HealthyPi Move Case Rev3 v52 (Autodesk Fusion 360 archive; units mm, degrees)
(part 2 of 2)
create_component "CreateComponent2"
create_component "CreateComponent3"
create_component "CreateComponent5"
create_component "CreateComponent7"
create_component "CreateComponent8"
create_component "CreateComponent9"
create_component "CreateComponent16"
create_component "CreateComponent21"
create_component "CreateComponent22"
create_component "CreateComponent24"
create_component "CreateComponent25"
create_component "CreateComponent26"
create_component "CreateComponent27"
create_component "CreateComponent28"
create_component "CreateComponent29"
create_component "CreateComponent30"
as_built_joint "As-built1"
create_component "CreateComponent31"
create_component "CreateComponent1"
create_component "CreateComponent35"
create_component "CreateComponent37"
create_component "CreateComponent38"
create_component "CreateComponent41"
create_component "CreateComponent42"
create_component "CreateComponent43"
create_component "CreateComponent44"
create_component "CreateComponent45"
create_component "CreateComponent46"
create_component "CreateComponent49"
create_component "CreateComponent51"
create_component "CreateComponent53"
create_component "CreateComponent54"
create_component "CreateComponent56"
create_component "CreateComponent57"
create_component "CreateComponent58"
create_component "CreateComponent59"
create_component "CreateComponent60"
named bodies: "Board"

design "pc_healthypi_move_bottom_pcb_v2"
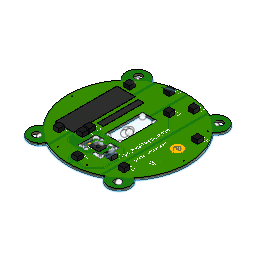
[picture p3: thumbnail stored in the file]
sketch "Outline" plane through (0, 0, 0) normal (0, 0, 1) x axis (1, 0, 0)
  line L1 (5.8203, -2.7998) -> (5.5496, -2.9972)
  line L2 (7, -1.2) -> (6.8643, -1.5063)
  line L3 (27.4, -1.2) -> (27, -1.4)
  line L4 (27.5357, -1.5063) -> (27.4, -1.2)
  line L5 (34.2527, 2.2023) -> (34.4146, 1.9091)
  line L6 (33.1, 3.4) -> (33.3707, 3.2026)
  line L7 (33.1, 30.9) -> (34.236, 29.4195)
  line L8 (28.8504, 37.2972) -> (29.1372, 37.4702)
  line L9 (28.0949, 36.6383) -> (28.3272, 36.8796)
  line L10 (27.8845, 36.3776) -> (28.0949, 36.6383)
  line L11 (27.4, 35.5) -> (27.5357, 35.8063)
  line L12 (7, 35.5) -> (8.7465, 36.3144)
  line L13 (6.3051, 36.6383) -> (6.5155, 36.3776)
  line L14 (6.0728, 36.8796) -> (6.3051, 36.6383)
  line L15 (1.0293, 31.0974) -> (0.7768, 31.3176)
  line L16 (1.3, 30.9) -> (1.0293, 31.0974)
  line L17 (1.3, 3.4) -> (0.164, 4.8805)
  line L18 (19.55, 11.6) -> (15.05, 11.6)
  line L19 (19.5805, 11.6013) -> (19.55, 11.6)
  line L20 (19.9, 24.35) -> (19.9, 11.95)
  line L21 (19.8987, 24.3805) -> (19.9, 24.35)
  line L22 (15.05, 24.7) -> (19.55, 24.7)
  line L23 (15.0195, 24.6987) -> (15.05, 24.7)
  line L24 (14.7, 11.95) -> (14.7, 24.35)
  line L25 (15.9, 3.4) -> (13.7, 3.4)
  line L26 (15.9305, 3.4013) -> (15.9, 3.4)
  line L27 (16.25, 4.05) -> (16.25, 3.75)
  line L28 (16.2487, 4.0805) -> (16.25, 4.05)
  line L29 (14.75, 4.4) -> (15.9, 4.4)
  line L30 (14.7151, 4.4015) -> (14.75, 4.4)
  line L31 (14.35, 8.45) -> (14.35, 4.8)
  line L32 (14.3513, 8.4805) -> (14.35, 8.45)
  line L33 (15.95, 8.8) -> (14.7, 8.8)
  line L34 (15.9761, 8.8011) -> (15.95, 8.8)
  line L35 (16.25, 9.5) -> (16.25, 9.1)
  line L36 (16.2489, 9.5261) -> (16.25, 9.5)
  line L37 (13.7, 9.8) -> (15.95, 9.8)
  line L38 (13.6695, 9.7987) -> (13.7, 9.8)
  line L39 (13.35, 3.75) -> (13.35, 9.45)
  line L40 (21, 3.4) -> (18.8, 3.4)
  line L41 (21.0305, 3.4013) -> (21, 3.4)
  line L42 (21.35, 9.45) -> (21.35, 3.75)
  line L43 (21.3487, 9.4805) -> (21.35, 9.45)
  line L44 (18.8, 9.8) -> (21, 9.8)
  line L45 (18.7695, 9.7987) -> (18.8, 9.8)
  line L46 (18.45, 9.15) -> (18.45, 9.45)
  line L47 (18.4513, 9.1195) -> (18.45, 9.15)
  line L48 (20, 8.8) -> (18.8, 8.8)
  line L49 (20.0305, 8.7987) -> (20, 8.8)
  line L50 (20.35, 4.75) -> (20.35, 8.45)
  line L51 (20.3487, 4.7195) -> (20.35, 4.75)
  line L52 (18.8, 4.4) -> (20, 4.4)
  line L53 (18.7695, 4.3987) -> (18.8, 4.4)
  line L54 (18.45, 3.75) -> (18.45, 4.05)
  arc A1 centre (3.4248, 0.2014) radius 3.84 clockwise from (5.5496, -2.9972) to (1.3, 3.4)
  arc A2 centre (3.4248, 0.2014) radius 3.84 clockwise from (6.8643, -1.5063) to (5.8203, -2.7998)
  arc A3 centre (17.1921, 17.9099) radius 21.6579 clockwise from (27, -1.4) to (7, -1.2)
  arc A4 centre (30.9752, 0.2014) radius 3.84 clockwise from (34.4146, 1.9091) to (27.5357, -1.5063)
  arc A5 centre (30.9752, 0.2014) radius 3.84 clockwise from (33.3707, 3.2026) to (34.2527, 2.2023)
  arc A6 centre (16.7133, 17.15) radius 21.3912 clockwise from (34.236, 29.4195) to (33.1, 3.4)
  arc A7 centre (30.9752, 34.0986) radius 3.84 clockwise from (29.1372, 37.4702) to (33.1, 30.9)
  arc A8 centre (30.9754, 34.0983) radius 3.8404 clockwise from (28.3272, 36.8796) to (28.8504, 37.2972)
  arc A9 centre (30.9751, 34.0985) radius 3.84 clockwise from (27.5357, 35.8063) to (27.8845, 36.3776)
  arc A10 centre (17.2, 15.906) radius 22.0899 clockwise from (8.7465, 36.3144) to (27.4, 35.5)
  arc A11 centre (3.4247, 34.0986) radius 3.8401 clockwise from (6.5155, 36.3776) to (7, 35.5)
  arc A12 centre (3.4248, 34.0986) radius 3.84 clockwise from (0.7768, 31.3176) to (6.0728, 36.8796)
  arc A13 centre (17.6866, 17.15) radius 21.3912 clockwise from (0.164, 4.8805) to (1.3, 30.9)
  arc A14 centre (15.05, 11.95) radius 0.35 clockwise from (15.05, 11.6) to (14.7, 11.95)
  arc A15 centre (19.55, 11.95) radius 0.35 clockwise from (19.9, 11.95) to (19.5805, 11.6013)
  arc A16 centre (19.55, 24.35) radius 0.35 clockwise from (19.55, 24.7) to (19.8987, 24.3805)
  arc A17 centre (15.05, 24.35) radius 0.35 clockwise from (14.7, 24.35) to (15.0195, 24.6987)
  arc A18 centre (13.7, 3.75) radius 0.35 clockwise from (13.7, 3.4) to (13.35, 3.75)
  arc A19 centre (15.9, 3.75) radius 0.35 clockwise from (16.25, 3.75) to (15.9305, 3.4013)
  arc A20 centre (15.9, 4.05) radius 0.35 clockwise from (15.9, 4.4) to (16.2487, 4.0805)
  arc A21 centre (14.75, 4.8) radius 0.4 clockwise from (14.7151, 4.4015) to (14.35, 4.8)
  arc A22 centre (14.7, 8.45) radius 0.35 clockwise from (14.3513, 8.4805) to (14.7, 8.8)
  arc A23 centre (15.95, 9.1) radius 0.3 clockwise from (16.25, 9.1) to (15.9761, 8.8011)
  arc A24 centre (15.95, 9.5) radius 0.3 clockwise from (15.95, 9.8) to (16.2489, 9.5261)
  arc A25 centre (13.7, 9.45) radius 0.35 clockwise from (13.35, 9.45) to (13.6695, 9.7987)
  arc A26 centre (18.8, 3.75) radius 0.35 clockwise from (18.8, 3.4) to (18.45, 3.75)
  arc A27 centre (21, 3.75) radius 0.35 clockwise from (21.35, 3.75) to (21.0305, 3.4013)
  arc A28 centre (21, 9.45) radius 0.35 clockwise from (21, 9.8) to (21.3487, 9.4805)
  arc A29 centre (18.8, 9.45) radius 0.35 clockwise from (18.45, 9.45) to (18.7695, 9.7987)
  arc A30 centre (18.8, 9.15) radius 0.35 clockwise from (18.8, 8.8) to (18.4513, 9.1195)
  arc A31 centre (20, 8.45) radius 0.35 clockwise from (20.0305, 8.7987) to (20.35, 8.45)
  arc A32 centre (20, 4.75) radius 0.35 clockwise from (20.3487, 4.7195) to (20, 4.4)
  arc A33 centre (18.8, 4.05) radius 0.35 clockwise from (18.45, 4.05) to (18.7695, 4.3987)
canvas "Canvas1" bodies "Board"
canvas "Canvas2" bodies "Board"
pcbhole "PCBHole1" HoleDepth 0.8 HoleDiameter 2.5 TipAngle 10313.2
pcbhole "PCBHole2" HoleDepth 0.8 HoleDiameter 2.5 TipAngle 10313.2
pcbhole "PCBHole3" HoleDepth 0.8 HoleDiameter 2.5 TipAngle 10313.2
pcbhole "PCBHole4" HoleDepth 0.8 HoleDiameter 2.5 TipAngle 10313.2
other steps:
box_primitive "BoxPrimitive1" DistanceX 14.25 DistanceY 2.04 DistanceZ 0.1 OffsetDistanceX 0 OffsetDistanceY 0
box_primitive "BoxPrimitive1" DistanceX 21.63 DistanceY 6.45 DistanceZ 0.1 OffsetDistanceX 0 OffsetDistanceY 0
box_primitive "BoxPrimitive1" DistanceX 3.65 DistanceY 3.127 DistanceZ 0.1 OffsetDistanceX 0 OffsetDistanceY 0
base_feature "Base Feature"
box_primitive "BoxPrimitive1" DistanceX 2 DistanceY 2 DistanceZ 1.365 OffsetDistanceX 0 OffsetDistanceY 0
extrude "Extrude1" sketch "Outline" blind 0.8 bodies "Board"
pcbextrude "PCBExtrude1"
create_component "CreateComponent1"
create_component "CreateComponent2"
create_component "CreateComponent4"
as_built_joint "As-built1"
create_component "CreateComponent5"
create_component "CreateComponent6"
create_component "CreateComponent7"
create_component "CreateComponent8"
create_component "CreateComponent9"
named bodies: "Board"

design "pc_healthypi_move_sensor_dual"
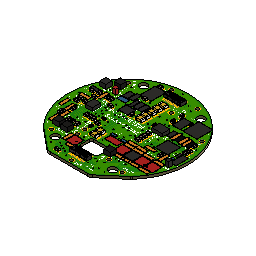
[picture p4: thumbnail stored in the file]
sketch "Outline" plane through (0, 0, 0) normal (0, 0, 1) x axis (1, 0, 0)
  line L1 (12.1, 0.4) -> (5.2, 6.1)
  line L2 (12.1693, 0.3516) -> (12.1, 0.4)
  line L3 (25.5, 0) -> (13.6, 0)
  line L4 (25.5727, -0.0005) -> (25.5, 0)
  line L5 (33.3, 6) -> (26.8, 0.4)
  line L6 (33.4, 6.1) -> (33.3, 6)
  line L7 (33.6273, 6.3481) -> (33.4, 6.1)
  line L8 (3.9028, 30.851) -> (4.9727, 32.1488)
  line L9 (21.6, 6.1) -> (17, 6.1)
  line L10 (21.661, 6.1027) -> (21.6, 6.1)
  line L11 (22.3, 9.8) -> (22.3, 6.8)
  line L12 (22.2973, 9.861) -> (22.3, 9.8)
  line L13 (17, 10.5) -> (21.6, 10.5)
  line L14 (16.939, 10.4973) -> (17, 10.5)
  line L15 (16.3, 6.8) -> (16.3, 9.8)
  arc A1 centre (13.3676, 2.1412) radius 2.1538 clockwise from (13.6, 0) to (12.1693, 0.3516)
  arc A2 centre (25.5512, 2.146) radius 2.1466 clockwise from (26.8, 0.4) to (25.5727, -0.0005)
  arc A3 centre (19.3, 19.2484) radius 19.2793 clockwise from (4.9727, 32.1488) to (33.6273, 6.3481)
  arc A4 centre (19.3, 19.2484) radius 19.2793 clockwise from (5.2, 6.1) to (3.9028, 30.851)
  arc A5 centre (17, 6.8) radius 0.7 clockwise from (17, 6.1) to (16.3, 6.8)
  arc A6 centre (21.6, 6.8) radius 0.7 clockwise from (22.3, 6.8) to (21.661, 6.1027)
  arc A7 centre (21.6, 9.8) radius 0.7 clockwise from (21.6, 10.5) to (22.2973, 9.861)
  arc A8 centre (17, 9.8) radius 0.7 clockwise from (16.3, 9.8) to (16.939, 10.4973)
canvas "Canvas1" bodies "Board"
canvas "Canvas2" bodies "Board"
pcbhole "PCBHole9" HoleDepth 0.8 HoleDiameter 2.5 TipAngle 10313.2
pcbhole "PCBHole10" HoleDepth 0.8 HoleDiameter 2.5 TipAngle 10313.2
pcbhole "PCBHole11" HoleDepth 0.8 HoleDiameter 2.5 TipAngle 10313.2
pcbhole "PCBHole12" HoleDepth 0.8 HoleDiameter 2.5 TipAngle 10313.2
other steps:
box_primitive "BoxPrimitive1" DistanceX 3.1 DistanceY 2.6 DistanceZ 0.1 OffsetDistanceX 0 OffsetDistanceY 0
box_primitive "BoxPrimitive1" DistanceX 2.997 DistanceY 1.017 DistanceZ 0.1 OffsetDistanceX 0 OffsetDistanceY 0
box_primitive "BoxPrimitive1" DistanceX 3.856 DistanceY 4.256 DistanceZ 1 OffsetDistanceX 0 OffsetDistanceY 0
box_primitive "BoxPrimitive1" DistanceX 14.25 DistanceY 2.04 DistanceZ 0.1 OffsetDistanceX 0 OffsetDistanceY 0
box_primitive "BoxPrimitive1" DistanceX 21.63 DistanceY 6.45 DistanceZ 0.1 OffsetDistanceX 0 OffsetDistanceY 0
base_feature "Base Feature1"
base_feature "Base Feature1"
box_primitive "BoxPrimitive1" DistanceX 5.175 DistanceY 4.55 DistanceZ 0.1 OffsetDistanceX 0 OffsetDistanceY 0
box_primitive "BoxPrimitive1" DistanceX 1.85 DistanceY 1.45 DistanceZ 1 OffsetDistanceX 0 OffsetDistanceY 0
box_primitive "BoxPrimitive1" DistanceX 2.515 DistanceY 3.302 DistanceZ 1 OffsetDistanceX 0 OffsetDistanceY 0
box_primitive "BoxPrimitive1" DistanceX 1.85 DistanceY 0.7 DistanceZ 1 OffsetDistanceX 0 OffsetDistanceY 0
box_primitive "BoxPrimitive1" DistanceX 3.815 DistanceY 2.6 DistanceZ 0.1 OffsetDistanceX 0 OffsetDistanceY 0
box_primitive "BoxPrimitive1" DistanceX 2.743 DistanceY 1.397 DistanceZ 0.1 OffsetDistanceX 0 OffsetDistanceY 0
box_primitive "BoxPrimitive1" DistanceX 2.743 DistanceY 1.397 DistanceZ 0.1 OffsetDistanceX 0 OffsetDistanceY 0
base_feature "Base Feature1"
base_feature "Base Feature1"
box_primitive "BoxPrimitive1" DistanceX 0.75 DistanceY 1.7 DistanceZ 0.1 OffsetDistanceX 0 OffsetDistanceY 0
box_primitive "BoxPrimitive1" DistanceX 2.451 DistanceY 1.351 DistanceZ 0.1 OffsetDistanceX 0 OffsetDistanceY 0
box_primitive "BoxPrimitive1" DistanceX 2.997 DistanceY 1.017 DistanceZ 0.1 OffsetDistanceX 0 OffsetDistanceY 0
box_primitive "BoxPrimitive1" DistanceX 3.003 DistanceY 3 DistanceZ 0.1 OffsetDistanceX 0 OffsetDistanceY 0
box_primitive "BoxPrimitive1" DistanceX 2.75 DistanceY 2.25 DistanceZ 1 OffsetDistanceX 0 OffsetDistanceY 0
box_primitive "BoxPrimitive1" DistanceX 8.8 DistanceY 5.55 DistanceZ 0.1 OffsetDistanceX 0 OffsetDistanceY 0
box_primitive "BoxPrimitive1" DistanceX 4.027 DistanceY 1.9 DistanceZ 0.1 OffsetDistanceX 0 OffsetDistanceY 0
box_primitive "BoxPrimitive1" DistanceX 2.45 DistanceY 1.65 DistanceZ 0.1 OffsetDistanceX 0 OffsetDistanceY 0
box_primitive "BoxPrimitive1" DistanceX 4.87 DistanceY 3.55 DistanceZ 0.1 OffsetDistanceX 0 OffsetDistanceY 0
box_primitive "BoxPrimitive1" DistanceX 4.127 DistanceY 4.127 DistanceZ 0.1 OffsetDistanceX 0 OffsetDistanceY 0
box_primitive "BoxPrimitive1" DistanceX 2.743 DistanceY 1.397 DistanceZ 0.1 OffsetDistanceX 0 OffsetDistanceY 0
base_feature "Base Feature1"
box_primitive "BoxPrimitive1" DistanceX 1.1 DistanceY 1.1 DistanceZ 1.654 OffsetDistanceX 0 OffsetDistanceY 0
box_primitive "BoxPrimitive1" DistanceX 2 DistanceY 2 DistanceZ 1.365 OffsetDistanceX 0 OffsetDistanceY 0
extrude "Extrude1" sketch "Outline" blind 0.8 bodies "Board"
pcbextrude "PCBExtrude1"
create_component "CreateComponent1"
create_component "CreateComponent2"
create_component "CreateComponent1"
create_component "CreateComponent2"
create_component "CreateComponent4"
create_component "CreateComponent5"
create_component "CreateComponent6"
create_component "CreateComponent7"
create_component "CreateComponent12"
create_component "CreateComponent13"
create_component "CreateComponent14"
create_component "CreateComponent15"
create_component "CreateComponent17"
create_component "CreateComponent18"
create_component "CreateComponent19"
create_component "CreateComponent22"
create_component "CreateComponent23"
as_built_joint "As-built1"
create_component "CreateComponent24"
create_component "CreateComponent25"
create_component "CreateComponent26"
create_component "CreateComponent27"
create_component "CreateComponent28"
create_component "CreateComponent29"
create_component "CreateComponent30"
create_component "CreateComponent31"
create_component "CreateComponent32"
create_component "CreateComponent33"
create_component "CreateComponent34"
create_component "CreateComponent35"
create_component "CreateComponent36"
create_component "CreateComponent37"
create_component "CreateComponent38"
create_component "CreateComponent39"
create_component "CreateComponent40"
named bodies: "Board"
